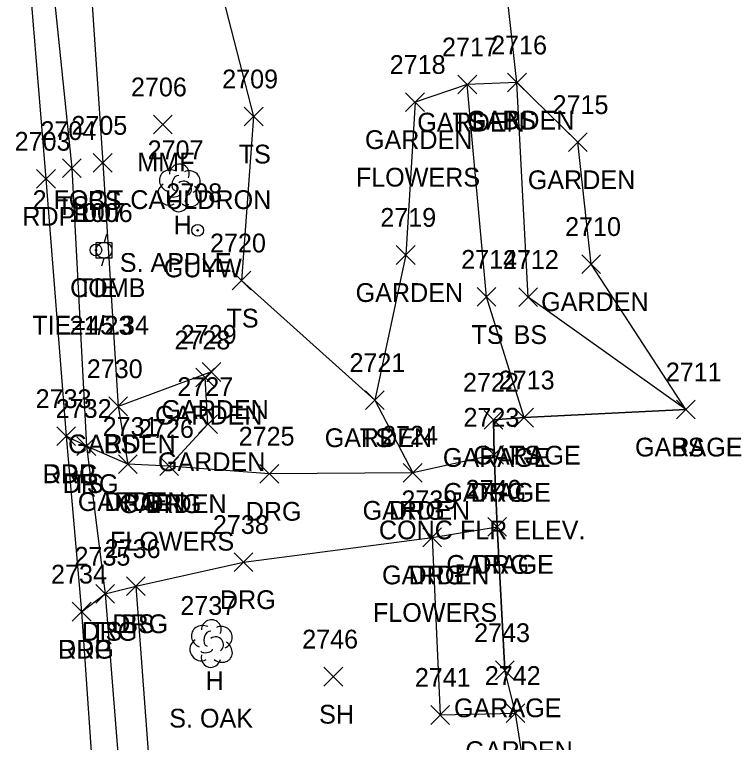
# Model space of a CAD drawing. Extents: x 1461855 to 1464118, y 556196 to 557441.
# Drawn here: x 1462404.4 to 1462481.8, y 556684.1 to 556761.6 of the extents above; entities that cross this region are included whole.
import ezdxf

# ---------------------------------------------------------------- set-up
doc = ezdxf.new("R2010")
doc.units = 0
for name, color, linetype in [('C_A', 7, 'Continuous'), ('C_C', 7, 'Continuous'), ('C_I', 7, 'Continuous'), ('CBP', 7, 'Continuous'), ('L_A', 7, 'Continuous'), ('L_C', 7, 'Continuous'), ('L_I', 7, 'Continuous'), ('L_TIC', 7, 'Continuous'), ('LAPB', 7, 'Continuous'), ('LBC', 7, 'Continuous'), ('LELB', 7, 'Continuous'), ('LSOGP', 7, 'Continuous'), ('LTD', 7, 'Continuous'), ('P_A', 7, 'Continuous'), ('P_I', 7, 'Continuous'), ('P_TIC', 7, 'Continuous'), ('PET', 7, 'Continuous'), ('R_A', 7, 'Continuous'), ('R_C', 7, 'Continuous'), ('R_I', 7, 'Continuous'), ('R_TIC', 7, 'Continuous'), ('RDG', 7, 'Continuous'), ('U_A', 7, 'Continuous'), ('U_C', 7, 'Continuous'), ('U_I', 7, 'Continuous'), ('UP', 7, 'Continuous'), ('UPGW', 7, 'Continuous')]:
    doc.layers.add(name, color=color, linetype=linetype)

msp = doc.modelspace()

# ---------------------------------------------------------------- linework, layer by layer
at = {"layer": 'CBP'}
for radius in [0.625, 0.0833]:
    msp.add_circle((1462413.042, 556736.536), radius, dxfattribs=at)
at = {"layer": 'L_TIC'}
for points in [[(1462451.583, 556753.157), (1462453.583, 556755.157)], [(1462453.583, 556753.157), (1462451.583, 556755.157)], [(1462451.583, 556753.157), (1462453.583, 556755.157)], [(1462453.583, 556753.157), (1462451.583, 556755.157)], [(1462456.869, 556753.367), (1462458.869, 556755.367)], [(1462458.869, 556753.367), (1462456.869, 556755.367)], [(1462456.869, 556753.367), (1462458.869, 556755.367)], [(1462458.869, 556753.367), (1462456.869, 556755.367)], [(1462446.018, 556751.293), (1462448.018, 556753.293)], [(1462448.018, 556751.293), (1462446.018, 556753.293)], [(1462428.833, 556749.754), (1462430.833, 556751.754)], [(1462430.833, 556749.754), (1462428.833, 556751.754)], [(1462419.169, 556748.901), (1462421.169, 556750.901)], [(1462421.169, 556748.901), (1462419.169, 556750.901)], [(1462463.356, 556747.018), (1462465.356, 556749.018)], [(1462465.356, 556747.018), (1462463.356, 556749.018)], [(1462412.767, 556744.811), (1462414.767, 556746.811)], [(1462414.767, 556744.811), (1462412.767, 556746.811)], [(1462409.476, 556744.251), (1462411.476, 556746.251)], [(1462411.476, 556744.251), (1462409.476, 556746.251)], [(1462445.024, 556735.008), (1462447.024, 556737.008)], [(1462447.024, 556735.008), (1462445.024, 556737.008)], [(1462464.776, 556734.034), (1462466.776, 556736.034)], [(1462466.776, 556734.034), (1462464.776, 556736.034)], [(1462427.54, 556732.285), (1462429.54, 556734.285)], [(1462429.54, 556732.285), (1462427.54, 556734.285)], [(1462453.623, 556730.541), (1462455.623, 556732.541)], [(1462455.623, 556730.541), (1462453.623, 556732.541)], [(1462458.07, 556730.526), (1462460.07, 556732.526)], [(1462460.07, 556730.526), (1462458.07, 556732.526)], [(1462424.346, 556722.551), (1462426.346, 556724.551)], [(1462426.346, 556722.551), (1462424.346, 556724.551)], [(1462423.669, 556721.952), (1462425.669, 556723.952)], [(1462425.669, 556721.952), (1462423.669, 556723.952)], [(1462441.733, 556719.549), (1462443.733, 556721.549)], [(1462443.733, 556719.549), (1462441.733, 556721.549)], [(1462441.733, 556719.549), (1462443.733, 556721.549)], [(1462443.733, 556719.549), (1462441.733, 556721.549)], [(1462414.416, 556718.891), (1462416.416, 556720.891)], [(1462416.416, 556718.891), (1462414.416, 556720.891)], [(1462414.416, 556718.891), (1462416.416, 556720.891)], [(1462416.416, 556718.891), (1462414.416, 556720.891)], [(1462474.843, 556718.549), (1462476.843, 556720.549)], [(1462476.843, 556718.549), (1462474.843, 556720.549)], [(1462474.843, 556718.549), (1462476.843, 556720.549)], [(1462476.843, 556718.549), (1462474.843, 556720.549)], [(1462457.623, 556717.689), (1462459.623, 556719.689)], [(1462459.623, 556717.689), (1462457.623, 556719.689)], [(1462457.623, 556717.689), (1462459.623, 556719.689)], [(1462459.623, 556717.689), (1462457.623, 556719.689)], [(1462423.974, 556716.989), (1462425.974, 556718.989)], [(1462425.974, 556716.989), (1462423.974, 556718.989)], [(1462454.383, 556717.445), (1462456.383, 556719.445)], [(1462456.383, 556717.445), (1462454.383, 556719.445)], [(1462411.025, 556714.66), (1462413.025, 556716.66)], [(1462413.025, 556714.66), (1462411.025, 556716.66)], [(1462454.436, 556713.728), (1462456.436, 556715.728)], [(1462456.436, 556713.728), (1462454.436, 556715.728)], [(1462415.449, 556712.742), (1462417.449, 556714.742)], [(1462417.449, 556712.742), (1462415.449, 556714.742)], [(1462419.841, 556712.528), (1462421.841, 556714.528)], [(1462421.841, 556712.528), (1462419.841, 556714.528)], [(1462445.767, 556711.814), (1462447.767, 556713.814)], [(1462447.767, 556711.814), (1462445.767, 556713.814)], [(1462454.757, 556706.057), (1462456.757, 556708.057)], [(1462456.757, 556706.057), (1462454.757, 556708.057)], [(1462447.835, 556704.937), (1462449.835, 556706.937)], [(1462449.835, 556704.937), (1462447.835, 556706.937)], [(1462416.293, 556699.736), (1462418.293, 556701.736)], [(1462418.293, 556699.736), (1462416.293, 556701.736)], [(1462413.021, 556698.927), (1462415.021, 556700.927)], [(1462415.021, 556698.927), (1462413.021, 556700.927)], [(1462455.569, 556690.783), (1462457.569, 556692.783)], [(1462457.569, 556690.783), (1462455.569, 556692.783)], [(1462437.318, 556690.102), (1462439.318, 556692.102)], [(1462439.318, 556690.102), (1462437.318, 556692.102)], [(1462448.688, 556686.022), (1462450.688, 556688.022)], [(1462450.688, 556686.022), (1462448.688, 556688.022)], [(1462456.706, 556686.223), (1462458.706, 556688.223)], [(1462458.706, 556686.223), (1462456.706, 556688.223)]]:
    msp.add_lwpolyline(points, dxfattribs=at)
at = {"layer": 'LAPB'}
for points in [[(1462465.776, 556735.034), (1462464.356, 556748.018), (1462457.869, 556754.367), (1462452.583, 556754.157), (1462447.018, 556752.293), (1462446.024, 556736.008), (1462442.733, 556720.549), (1462446.767, 556712.814)], [(1462420.841, 556713.528), (1462424.974, 556717.989), (1462424.669, 556722.952), (1462425.346, 556723.551), (1462415.416, 556719.891), (1462416.449, 556713.742)], [(1462448.835, 556705.937), (1462449.688, 556687.022), (1462457.706, 556687.223)]]:
    msp.add_lwpolyline(points, dxfattribs=at)
at = {"layer": 'LBC'}
msp.add_lwpolyline([(1462475.843, 556719.549), (1462458.623, 556718.689), (1462455.383, 556718.445), (1462455.436, 556714.728), (1462455.757, 556707.057), (1462456.569, 556691.783)], dxfattribs=at)
at = {"layer": 'LELB'}
for points in [[(1462398.71, 556863.574), (1462402.391, 556852.24), (1462404.798, 556832.693), (1462410.819, 556809.539), (1462407.679, 556805.323), (1462406.455, 556784.092), (1462410.476, 556745.251), (1462412.025, 556715.66), (1462414.021, 556699.927), (1462415.956, 556675.834), (1462416.655, 556662.842), (1462419.224, 556640.169), (1462421.298, 556615.254), (1462423.719, 556596.606), (1462425.734, 556595.598), (1462438.5, 556592.477), (1462441.607, 556592.429), (1462458.64, 556594.551)], [(1462412.599, 556781.566), (1462411.938, 556773.142), (1462413.767, 556745.811), (1462415.416, 556719.891)], [(1462423.559, 556775.02), (1462429.833, 556750.754), (1462428.54, 556733.285), (1462442.733, 556720.549)], [(1462475.843, 556719.549), (1462459.07, 556731.526), (1462457.869, 556754.367)], [(1462458.623, 556718.689), (1462454.623, 556731.541), (1462452.583, 556754.157)], [(1462417.293, 556700.736), (1462419.133, 556675.922), (1462417.807, 556664.464)]]:
    msp.add_lwpolyline(points, dxfattribs=at)
at = {"layer": 'LSOGP'}
msp.add_lwpolyline([(1462459.317, 556677.129), (1462457.706, 556687.223), (1462456.569, 556691.783), (1462455.757, 556707.057), (1462455.436, 556714.728), (1462455.383, 556718.445), (1462458.623, 556718.689), (1462475.843, 556719.549), (1462465.776, 556735.034), (1462464.356, 556748.018), (1462457.869, 556754.367), (1462455.559, 556775.229), (1462451.217, 556788.799), (1462452.547, 556795.568), (1462449.934, 556798.493), (1462436.265, 556801.642), (1462428.47, 556801.403), (1462427.807, 556811.266), (1462426.908, 556833.994), (1462432.372, 556848.728), (1462434.47, 556867.36), (1462437.774, 556881.647)], dxfattribs=at)
at = {"layer": 'LTD'}
for p, q in [((1462421.885, 556743.208), (1462421.885, 556743.208)), ((1462421.885, 556743.208), (1462421.885, 556743.208)), ((1462425.29, 556694.683), (1462425.29, 556694.683)), ((1462425.29, 556694.683), (1462425.29, 556694.683))]:
    msp.add_line(p, q, dxfattribs=at)
for centre in [(1462421.932, 556744.642), (1462425.336, 556696.117)]:
    msp.add_arc(centre, 1.047, 335.52715, 180.95627, dxfattribs=at)
for centre, major_axis, ratio, start_param, end_param in [((1462421.093, 556743.875), (1.21, -0.512), 0.895232, 1.570796, 4.712389), ((1462422.926, 556743.792), (-1.141, -0.483), 0.949671, 1.570796, 4.712389), ((1462421.676, 556743.666), (-0.208, -0.792), 0.645439, 3.141593, 6.283185), ((1462420.802, 556742.5), (0.584, -1.042), 0.959034, 3.141593, 6.283185), ((1462422.385, 556743.042), (-0.5, 0.667), 0.989748, 3.141593, 6.283185), ((1462422.885, 556742.375), (-1.09, 0.792), 0.841452, 1.570796, 4.712389), ((1462421.885, 556741.708), (0.265, 1.061), 0.942809, 1.570796, 4.712389), ((1462421.427, 556742.458), (-0.625, -0.083), 0.423636, 0, 3.141593), ((1462424.498, 556695.35), (1.21, -0.512), 0.895232, 1.570796, 4.712389), ((1462426.331, 556695.267), (-1.141, -0.483), 0.949671, 1.570796, 4.712389), ((1462425.081, 556695.142), (-0.208, -0.792), 0.645439, 3.141593, 6.283185), ((1462425.79, 556694.517), (-0.5, 0.667), 0.989748, 3.141593, 6.283185), ((1462424.206, 556693.975), (0.584, -1.042), 0.959034, 3.141593, 6.283185), ((1462426.29, 556693.85), (-1.09, 0.792), 0.841452, 1.570796, 4.712389), ((1462424.831, 556693.933), (-0.625, -0.083), 0.423636, 0, 3.141593), ((1462425.29, 556693.183), (0.265, 1.061), 0.942809, 1.570796, 4.712389)]:
    msp.add_ellipse(centre, major_axis=major_axis, ratio=ratio, start_param=start_param, end_param=end_param, dxfattribs=at)
at = {"layer": 'P_TIC'}
for points in [[(1462406.724, 556743.118), (1462408.724, 556745.118)], [(1462408.724, 556743.118), (1462406.724, 556745.118)], [(1462408.885, 556715.707), (1462410.885, 556717.707)], [(1462410.885, 556715.707), (1462408.885, 556717.707)], [(1462410.525, 556697.02), (1462412.525, 556699.02)], [(1462412.525, 556697.02), (1462410.525, 556699.02)]]:
    msp.add_lwpolyline(points, dxfattribs=at)
at = {"layer": 'PET'}
msp.add_lwpolyline([(1462383.886, 557021.818), (1462384.579, 557006.231), (1462385.506, 556984.294), (1462388.374, 556948.727), (1462389.95, 556932.539), (1462392.027, 556911.534), (1462394.302, 556882.812), (1462397.759, 556851.931), (1462399.645, 556831.993), (1462404.017, 556789.032), (1462407.724, 556744.118), (1462409.885, 556716.707), (1462411.525, 556698.02), (1462413.038, 556675.92), (1462416.6, 556635.991), (1462419.6, 556600.471)], dxfattribs=at)
at = {"layer": 'R_TIC'}
for points in [[(1462408.885, 556715.707), (1462410.885, 556717.707)], [(1462410.885, 556715.707), (1462408.885, 556717.707)], [(1462411.025, 556714.66), (1462413.025, 556716.66)], [(1462413.025, 556714.66), (1462411.025, 556716.66)], [(1462454.436, 556713.728), (1462456.436, 556715.728)], [(1462456.436, 556713.728), (1462454.436, 556715.728)], [(1462415.449, 556712.742), (1462417.449, 556714.742)], [(1462417.449, 556712.742), (1462415.449, 556714.742)], [(1462419.841, 556712.528), (1462421.841, 556714.528)], [(1462421.841, 556712.528), (1462419.841, 556714.528)], [(1462430.503, 556711.711), (1462432.503, 556713.711)], [(1462432.503, 556711.711), (1462430.503, 556713.711)], [(1462445.767, 556711.814), (1462447.767, 556713.814)], [(1462447.767, 556711.814), (1462445.767, 556713.814)], [(1462454.757, 556706.057), (1462456.757, 556708.057)], [(1462456.757, 556706.057), (1462454.757, 556708.057)], [(1462447.835, 556704.937), (1462449.835, 556706.937)], [(1462449.835, 556704.937), (1462447.835, 556706.937)], [(1462427.756, 556702.302), (1462429.756, 556704.302)], [(1462429.756, 556702.302), (1462427.756, 556704.302)], [(1462416.293, 556699.736), (1462418.293, 556701.736)], [(1462418.293, 556699.736), (1462416.293, 556701.736)], [(1462413.021, 556698.927), (1462415.021, 556700.927)], [(1462415.021, 556698.927), (1462413.021, 556700.927)], [(1462410.525, 556697.02), (1462412.525, 556699.02)], [(1462412.525, 556697.02), (1462410.525, 556699.02)]]:
    msp.add_lwpolyline(points, dxfattribs=at)
at = {"layer": 'RDG'}
for points in [[(1462455.436, 556714.728), (1462446.767, 556712.814), (1462431.503, 556712.711), (1462420.841, 556713.528), (1462416.449, 556713.742), (1462412.025, 556715.66), (1462409.885, 556716.707)], [(1462411.525, 556698.02), (1462414.021, 556699.927), (1462417.293, 556700.736), (1462428.756, 556703.302), (1462448.835, 556705.937), (1462455.757, 556707.057)]]:
    msp.add_lwpolyline(points, dxfattribs=at)
at = {"layer": 'UP'}
for p, q in [((1462414.157, 556738.186), (1462413.907, 556737.353)), ((1462413.074, 556735.686), (1462413.074, 556737.353)), ((1462413.074, 556737.353), (1462414.741, 556737.353)), ((1462414.741, 556737.353), (1462414.741, 556735.686)), ((1462413.907, 556736.519), (1462413.907, 556736.519)), ((1462414.741, 556735.686), (1462413.074, 556735.686)), ((1462413.657, 556734.853), (1462413.907, 556735.686))]:
    msp.add_line(p, q, dxfattribs=at)
msp.add_circle((1462413.907, 556736.519), 0.833, dxfattribs=at)
at = {"layer": 'UPGW'}
for radius in [0.625, 0.0833]:
    msp.add_circle((1462423.872, 556738.632), radius, dxfattribs=at)

# ---------------------------------------------------------------- texts
at = {"layer": 'C_A'}
msp.add_text('TIE', height=2, dxfattribs=at).set_placement((1462411.12, 556731.536))
at = {"layer": 'C_C'}
msp.add_text('TIE=45.34', height=2, dxfattribs=at).set_placement((1462406.27, 556727.536))
at = {"layer": 'C_I'}
msp.add_text('1007', height=2, dxfattribs=at).set_placement((1462410.191, 556739.536))
at = {"layer": 'L_A'}
for s, p in [('GARDEN', (1462452.538, 556749.367)), ('BS', (1462456.31, 556749.367)), ('GARDEN', (1462447.252, 556749.157)), ('TS', (1462450.992, 556749.157)), ('GARDEN', (1462441.687, 556747.293)), ('TS', (1462428.242, 556745.754)), ('MMF', (1462417.452, 556744.901)), ('GARDEN', (1462459.025, 556743.018)), ('BS', (1462412.208, 556740.811)), ('TS', (1462408.885, 556740.251)), ('H', (1462421.318, 556738.208)), ('GARDEN', (1462440.694, 556731.008)), ('GARDEN', (1462460.445, 556730.034)), ('TS', (1462426.949, 556728.285)), ('TS', (1462453.033, 556726.541)), ('BS', (1462457.511, 556726.526)), ('GARDEN', (1462420.015, 556718.551)), ('GARDEN', (1462419.338, 556717.952)), ('GARDEN', (1462437.402, 556715.549)), ('TS', (1462441.142, 556715.549)), ('GARDEN', (1462410.085, 556714.891)), ('BS', (1462413.857, 556714.891)), ('GARAGE', (1462470.441, 556714.549)), ('BS', (1462474.283, 556714.549)), ('GARAGE', (1462453.222, 556713.689)), ('TS', (1462457.033, 556713.689)), ('GARDEN', (1462419.643, 556712.989)), ('GARAGE', (1462449.981, 556713.445)), ('TS', (1462410.434, 556710.66)), ('GARAGE', (1462450.035, 556709.728)), ('GARDEN', (1462411.118, 556708.742)), ('GARDEN', (1462415.51, 556708.528)), ('GARDEN', (1462441.436, 556707.814)), ('GARAGE', (1462450.355, 556702.057)), ('GARDEN', (1462443.505, 556700.937)), ('BS', (1462415.734, 556695.736)), ('TS', (1462412.431, 556694.927)), ('H', (1462424.723, 556689.683)), ('GARAGE', (1462451.167, 556686.783)), ('SH', (1462436.807, 556686.102)), ('GARDEN', (1462452.375, 556682.223))]:
    msp.add_text(s, height=2, dxfattribs=at).set_placement(p)
at = {"layer": 'L_C'}
for s, p in [('FLOWERS', (1462440.718, 556743.293)), ('2 FOOT CAULDRON', (1462406.303, 556740.901)), ('S. APPLE', (1462415.586, 556734.208)), ('CONC FLR ELEV.', (1462443.169, 556705.728)), ('S. OAK', (1462420.849, 556685.683))]:
    msp.add_text(s, height=2, dxfattribs=at).set_placement(p)
at = {"layer": 'L_I'}
for s, p in [('2717', (1462449.89, 556757.157)), ('2717', (1462449.89, 556757.157)), ('2716', (1462455.121, 556757.367)), ('2716', (1462455.121, 556757.367)), ('2718', (1462444.325, 556755.293)), ('2709', (1462426.486, 556753.754)), ('2706', (1462416.775, 556752.901)), ('2715', (1462461.663, 556751.018)), ('2705', (1462410.429, 556748.811)), ('2704', (1462407.137, 556748.251)), ('2707', (1462418.546, 556746.208)), ('2719', (1462443.323, 556739.008)), ('2710', (1462462.996, 556738.034)), ('2720', (1462425.193, 556736.285)), ('2714', (1462451.93, 556734.541)), ('2712', (1462456.377, 556734.526)), ('2729', (1462422.078, 556726.551)), ('2728', (1462421.409, 556725.952)), ('2730', (1462412.07, 556722.891)), ('2730', (1462412.07, 556722.891)), ('2721', (1462440.04, 556723.549)), ('2721', (1462440.04, 556723.549)), ('2711', (1462473.717, 556722.549)), ('2711', (1462473.717, 556722.549)), ('2722', (1462452.123, 556721.445)), ('2713', (1462455.93, 556721.689)), ('2713', (1462455.93, 556721.689)), ('2727', (1462421.714, 556720.989)), ('2732', (1462408.765, 556718.66)), ('2723', (1462452.177, 556717.728)), ('2731', (1462413.756, 556716.742)), ('2726', (1462417.526, 556716.528)), ('2724', (1462443.507, 556715.814)), ('2740', (1462452.41, 556710.057)), ('2739', (1462445.568, 556708.937)), ('2736', (1462413.978, 556703.736)), ('2735', (1462410.761, 556702.927)), ('2737', (1462422.03, 556697.683)), ('2743', (1462453.309, 556694.783)), ('2746', (1462435.003, 556694.102)), ('2741', (1462446.995, 556690.022)), ('2742', (1462454.446, 556690.223))]:
    msp.add_text(s, height=2, dxfattribs=at).set_placement(p)
at = {"layer": 'P_A'}
for p in [(1462405.212, 556739.118), (1462407.373, 556711.707), (1462409.013, 556693.02)]:
    msp.add_text('RDP', height=2, dxfattribs=at).set_placement(p)
at = {"layer": 'P_I'}
for s, p in [('2703', (1462404.386, 556747.118)), ('2733', (1462406.625, 556719.707)), ('2734', (1462408.265, 556701.02))]:
    msp.add_text(s, height=2, dxfattribs=at).set_placement(p)
at = {"layer": 'R_A'}
for p in [(1462407.373, 556711.707), (1462409.513, 556710.66), (1462452.925, 556709.728), (1462413.937, 556708.742), (1462418.329, 556708.528), (1462428.991, 556707.711), (1462444.255, 556707.814), (1462453.245, 556702.057), (1462446.324, 556700.937), (1462426.244, 556698.302), (1462414.781, 556695.736), (1462411.509, 556694.927), (1462409.013, 556693.02)]:
    msp.add_text('DRG', height=2, dxfattribs=at).set_placement(p)
at = {"layer": 'R_C'}
for p in [(1462414.541, 556704.528), (1462442.536, 556696.937)]:
    msp.add_text('FLOWERS', height=2, dxfattribs=at).set_placement(p)
at = {"layer": 'R_I'}
for s, p in [('2733', (1462406.625, 556719.707)), ('2732', (1462408.765, 556718.66)), ('2723', (1462452.177, 556717.728)), ('2731', (1462413.756, 556716.742)), ('2726', (1462417.526, 556716.528)), ('2725', (1462428.243, 556715.711)), ('2724', (1462443.507, 556715.814)), ('2740', (1462452.41, 556710.057)), ('2739', (1462445.568, 556708.937)), ('2738', (1462425.496, 556706.302)), ('2736', (1462413.978, 556703.736)), ('2735', (1462410.761, 556702.927)), ('2734', (1462408.265, 556701.02))]:
    msp.add_text(s, height=2, dxfattribs=at).set_placement(p)
at = {"layer": 'U_A'}
for s, p in [('GUYW', (1462420.266, 556733.632)), ('COMB', (1462410.293, 556731.519))]:
    msp.add_text(s, height=2, dxfattribs=at).set_placement(p)
at = {"layer": 'U_C'}
msp.add_text('21/23', height=2, dxfattribs=at).set_placement((1462410.238, 556727.519))
at = {"layer": 'U_I'}
for s, p in [('2708', (1462420.534, 556741.632)), ('1006', (1462411.002, 556739.519))]:
    msp.add_text(s, height=2, dxfattribs=at).set_placement(p)

doc.saveas('drawing.dxf')
